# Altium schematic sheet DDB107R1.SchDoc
size A4; SheetNumber: 1; SheetTotal: 1
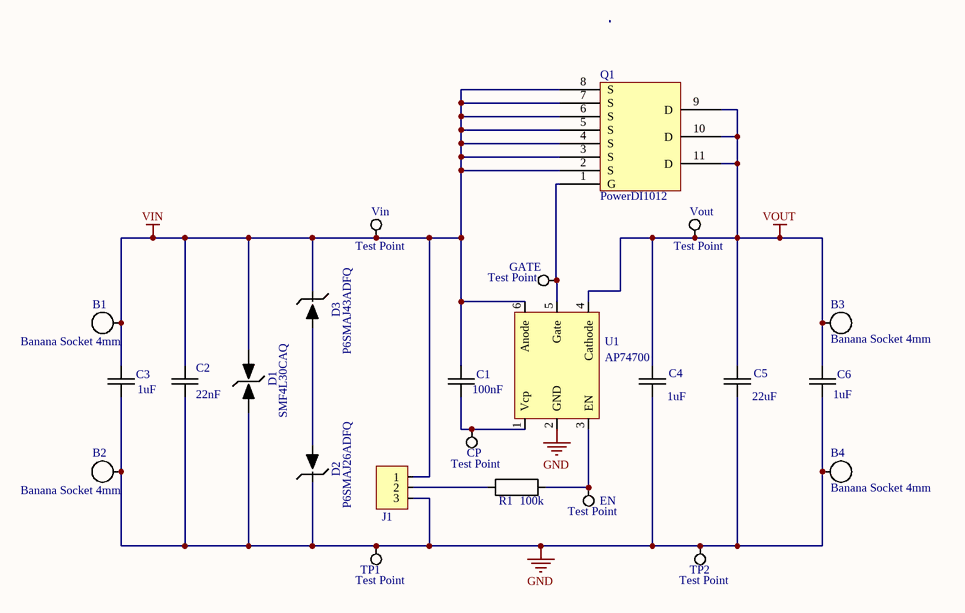
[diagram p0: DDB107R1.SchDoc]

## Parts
B1  Banana Socket 4mm  [Banana Plug]
B2  Banana Socket 4mm  [Banana Plug]
B3  Banana Socket 4mm  [Banana Plug]
B4  Banana Socket 4mm  [Banana Plug]
C1  Capacitor  [0805]  (value not drawn)
C2  Capacitor  [0805]  (value not drawn)
C3  Capacitor  [0805]  (value not drawn)
C4  Capacitor  [0805]  (value not drawn)
C5  Capacitor  [Case F Cap]  (value not drawn)
C6  Capacitor  [0805]  (value not drawn)
CP  Test Point  [TestPoint]
D1  SMF4L30CAQ  [SMF4Lxx(C)AQ]
D2  P6SMAJ26ADFQ  [P6SMAJxxADFQ]
D3  P6SMAJ43ADFQ  [P6SMAJxxADFQ]
EN  Test Point  [TestPoint]
GATE  Test Point  [TestPoint]
J1  3W header  [0.1" 3W]  (value not drawn)
Q1  PowerDI1012  [PowerDI1012-8L]
R1  Resistance  [0603]  (value not drawn)
TP1  Test Point  [TestPoint]
TP2  Test Point  [TestPoint]
U1  AP74700  [SOT26]
Vin  Test Point  [TestPoint]
Vout  Test Point  [TestPoint]

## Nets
GND: B2.1 B4.1 C2.1 C3.1 C4.1 C5.2 C6.1 D1.1 D2.0 J1.3 TP1.1 TP2.1 U1.2(GND)
VIN: B1.1 C1.2 C2.2 C3.2 D1.0 D3.0 J1.1 Q1.2(S) Q1.3(S) Q1.4(S) Q1.5(S) Q1.6(S) Q1.7(S) Q1.8(S) U1.6(Anode) Vin.1
VOUT: B3.1 C4.2 C5.1 C6.2 Q1.9(D) Q1.10(D) Q1.11(D) U1.4(Cathode) Vout.1
NetC1_1: C1.1 CP.1 U1.1(Vcp)
NetD2_1: D2.1 D3.1
NetEN_1: EN.1 R1.2 U1.3(EN)
NetGATE_1: GATE.1 Q1.1(G) U1.5(Gate)
NetJ1_2: J1.2 R1.1

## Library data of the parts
D1 = SMF4Lxx(C)AQ: TVS Device
D2 D3 = P6SMAJxxADFQ: TVS Device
